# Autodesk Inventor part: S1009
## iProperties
Author: Administrator
Revision Number: A
Shininess: 41.0
PropertySet Name: _Private Model Information
Created: 2000-11
Part Number: S1009
Project: ACME
Description: SCREW, 8-32 X .19L HEX SKT
Document SubType Name: Modeling
Standard: ANSI B18.3 - No. 8 - 32 x 0.19
Designer: E. MOSS
Control State: 0
Master: False
Checked Out: False
PropertySet Name: Design Tracking Control
Density: 0.0
Volumn: 0.0
Area: 0.0
PropertySet Name: Model Information
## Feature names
1. Base1
